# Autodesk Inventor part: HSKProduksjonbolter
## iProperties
Created: 2009-12
Part Number: HSKProduksjonbolter
Document SubType Name: Modeling
Designer: a31733
Density: 1 g/cm^3
Author: a31733
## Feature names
1. Circular Pattern1
2. Extrusion1
3. Loft1
4. Extrusion2
5. Extrusion4
6. Revolution1
7. Fillet5
8. Fillet6
9. Extrusion5
10. Fillet7
11. Extrusion6
12. Extrusion7
13. Circular Pattern2
14. Hole1
